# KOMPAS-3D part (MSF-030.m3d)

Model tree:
1. Ось X
2. Ось Y
3. Ось Z
4. Начало координат  (labels: Операция без истории:1)

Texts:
  Линия-выноска #1
  Линия-выноска #2
  Линия-выноска #3
  Отклонения формы и база
  Марка координационной оси
  Марка/позиционное обозначение с линией-выноской
  Марка/позиционное обозначение на линии
  Марка/позиционное обозначение без линии-выноски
